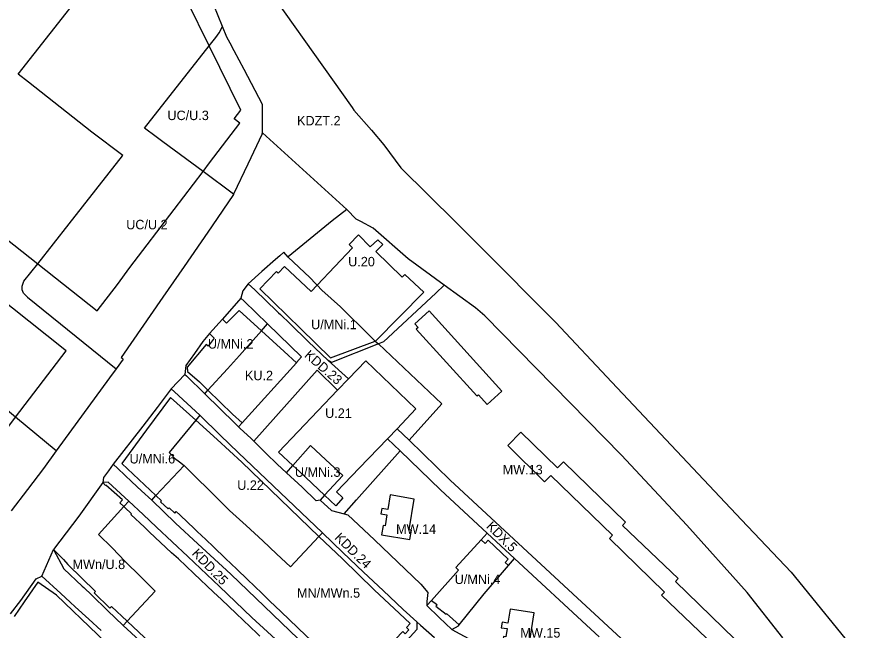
# Model space of a CAD drawing. Extents: x 7425067 to 7426806, y 5549054 to 5550619.
# Drawn here: x 7426359 to 7426806.4, y 5549627.2 to 5549951.6 of the extents above; entities that cross this region are included whole.
import ezdxf

# ---------------------------------------------------------------- set-up
doc = ezdxf.new("R2010")
doc.units = 0
for name, color, linetype in [('LIN_Linia Zabudowy Nieprzekraczalna', 7, 'Continuous'), ('LIN_linia zabudowy obowiązująca', 7, 'Continuous'), ('LIN_linie_rozgraniczajace', 7, 'Continuous'), ('TXT_Oznaczenia_przeznaczen', 7, 'Continuous')]:
    doc.layers.add(name, color=color, linetype=linetype)

msp = doc.modelspace()

# ---------------------------------------------------------------- linework, layer by layer
at = {"layer": 'LIN_Linia Zabudowy Nieprzekraczalna'}
for points in [[(7426574.3701, 5549805.9242), (7426564.36, 5549815.27), (7426562.95, 5549813.85), (7426548.97, 5549827.49), (7426552.62, 5549831.22), (7426550.08, 5549833.7), (7426545.97, 5549829.96), (7426539.76, 5549836.22), (7426534.88, 5549831.19), (7426536.67, 5549829.37), (7426517.9345, 5549809.6705)], [(7426548.7684, 5549780.0786), (7426574.3701, 5549805.9242)], [(7426525.0284, 5549771.1488), (7426548.73, 5549780.0641), (7426548.7684, 5549780.0786)], [(7426440.2683, 5549750.2788), (7426427.54, 5549733.14), (7426414.5439, 5549715.4054)], [(7426538.0268, 5549599.6257), (7426544.74, 5549606.81), (7426559.36, 5549622.35), (7426563.29, 5549626.51), (7426564.58, 5549625.28), (7426566.52, 5549627.33), (7426565.24, 5549628.54), (7426567.25, 5549630.67), (7426561.59, 5549636.03), (7426548.12, 5549648.56), (7426531.28, 5549664.88), (7426518.913, 5549676.7566), (7426478.07, 5549715.98), (7426464.99, 5549727.97), (7426453.6444, 5549738.2083), (7426440.2683, 5549750.2788)], [(7426414.5439, 5549715.4054), (7426432.6235, 5549698.32), (7426435.47, 5549695.63), (7426435, 5549695.1), (7426439.11, 5549691.3), (7426439.66, 5549691.9), (7426442.66, 5549689.14)], [(7426413.4908, 5549694.479), (7426414.9602, 5549696.0898), (7426406.0488, 5549703.8503), (7426405.97, 5549703.75), (7426404.43, 5549705.26), (7426391.71, 5549687.39), (7426378.39, 5549669.82)], [(7426426.5198, 5549681.588), (7426426.54, 5549681.61), (7426419.36, 5549688.41), (7426419.7, 5549688.77), (7426416.1, 5549692.08), (7426415.6453, 5549692.4981), (7426413.4908, 5549694.479)], [(7426442.66, 5549689.14), (7426443.3845, 5549689.9043), (7426445.3474, 5549688.063), (7426453.04, 5549680.77), (7426454.4822, 5549679.4051), (7426458.9674, 5549675.0954), (7426463.0302, 5549671.2622), (7426469.4399, 5549665.1439), (7426475.3736, 5549659.3903), (7426481.0322, 5549653.9703), (7426484.8352, 5549650.3881), (7426488.7822, 5549646.5623), (7426492.7561, 5549642.6881), (7426498.8215, 5549636.8419), (7426511.9317, 5549624.3494), (7426519.6144, 5549617.2769), (7426525.2257, 5549611.917), (7426529.8193, 5549607.5641), (7426538.0268, 5549599.6257)], [(7426487.6123, 5549624.0024), (7426486.1182, 5549625.4194), (7426475.0591, 5549635.938), (7426467.2851, 5549643.3718), (7426463.1098, 5549647.3578), (7426452.6961, 5549657.1819), (7426444.552, 5549664.9118), (7426440.8931, 5549668.0124), (7426429.2534, 5549678.9537), (7426426.5198, 5549681.588)], [(7426619.2615, 5549661.3404), (7426617.5, 5549663.0032), (7426619.13, 5549664.74), (7426608.5386, 5549674.7495), (7426606.8998, 5549673.0091), (7426604.7557, 5549675.0331)], [(7426378.39, 5549669.82), (7426383.61, 5549664.48), (7426386.01, 5549661.89), (7426400.55, 5549647.58), (7426399.82, 5549646.84), (7426408.17, 5549638.76), (7426409.02, 5549639.64), (7426417.3229, 5549631.8468), (7426444.72, 5549606.26), (7426460.04, 5549591.38), (7426467.6303, 5549584.2897), (7426477.25, 5549575.34), (7426477.5977, 5549575.714)], [(7426370.03, 5549652.54), (7426362.92, 5549642.18), (7426357.542, 5549634.3437)], [(7426413.6, 5549613.31), (7426401.6206, 5549624.8545), (7426380, 5549645.69), (7426370.03, 5549652.54)], [(7426578.398, 5549642.8706), (7426581.1286, 5549640.8896), (7426581.3939, 5549640.645), (7426580.79, 5549639.9), (7426586.15, 5549635.55), (7426586.4957, 5549635.9758), (7426593.1091, 5549629.933)]]:
    msp.add_lwpolyline(points, dxfattribs=at)
at = {"layer": 'LIN_linia zabudowy obowiązująca'}
for points in [[(7426477.01, 5549895.39), (7426474.02, 5549897.65), (7426477.58, 5549902.29), (7426460.7502, 5549936.2646), (7426449.26, 5549959.46), (7426441.71, 5549965.17), (7426422.62, 5549980.1), (7426417.53, 5549983.98), (7426417.78, 5549984.29), (7426412.3933, 5549988.5089), (7426402.65, 5549996.14), (7426401.75, 5549997.21), (7426363.71, 5550027.01)], [(7426265.8603, 5549903.2149), (7426320, 5549860.43), (7426369.9917, 5549820.9231), (7426401.5017, 5549796.0217)], [(7426442.32, 5549849.64), (7426457.5123, 5549869.788), (7426460.99, 5549874.4), (7426477.01, 5549895.39)], [(7426385.0744, 5549774.9325), (7426384.36, 5549775.5), (7426281.18, 5549857.47)], [(7426401.5017, 5549796.0217), (7426412.16, 5549809.96), (7426418.81, 5549818.96), (7426442.32, 5549849.64)], [(7426500.6894, 5549819.4961), (7426497.35, 5549816.03), (7426496.46, 5549816.89), (7426487.582, 5549807.7023)], [(7426514.6954, 5549806.2648), (7426500.6894, 5549819.4961)], [(7426487.582, 5549807.7023), (7426509.21, 5549786.59), (7426525.0284, 5549771.1488)], [(7426517.9345, 5549809.6705), (7426514.6954, 5549806.2648)], [(7426476.6068, 5549796.3443), (7426469.9988, 5549789.5057)], [(7426506.9179, 5549768.6433), (7426500.4, 5549774.6), (7426488.4327, 5549785.5368), (7426476.6068, 5549796.3443)], [(7426577.29, 5549796.04), (7426569.61, 5549789.15), (7426571.33, 5549787.24), (7426570.38, 5549786.39), (7426602.55, 5549751.06), (7426603.29, 5549751.72), (7426607.92, 5549746.56)], [(7426615.7, 5549753.6), (7426577.29, 5549796.04)], [(7426467.79, 5549791.63), (7426460.92, 5549784.18), (7426463.48, 5549781.67), (7426460.24, 5549777.47)], [(7426467.79, 5549791.63), (7426469.62, 5549789.87), (7426469.9988, 5549789.5057)], [(7426460.24, 5549777.47), (7426459.2, 5549778.34), (7426449.05, 5549766.29)], [(7426346.0059, 5549723.7436), (7426358.2546, 5549739.7922), (7426385.0744, 5549774.9325)], [(7426478.1914, 5549736.7716), (7426506.9179, 5549768.6433)], [(7426543.62, 5549769.68), (7426534.51, 5549760.15), (7426528.73, 5549754.1)], [(7426560.25, 5549733.73), (7426570.2485, 5549744.1648), (7426543.62, 5549769.68)], [(7426449.05, 5549766.29), (7426449.32, 5549763.94), (7426455.57, 5549758.5), (7426460.0965, 5549754.0969), (7426473.17, 5549741.38), (7426478.1914, 5549736.7716)], [(7426528.73, 5549754.1), (7426497.5593, 5549721.3931)], [(7426607.92, 5549746.56), (7426615.7, 5549753.6)], [(7426540.26, 5549712.91), (7426560.25, 5549733.73)], [(7426739.09, 5549622.43), (7426707.55, 5549652.9), (7426709.02, 5549654.42), (7426679.63, 5549682.6), (7426681.22, 5549684.26), (7426648.41, 5549716.18), (7426645.18, 5549712.98), (7426625.8, 5549731.91), (7426618.88, 5549724.83), (7426638.3, 5549705.72), (7426641.59, 5549709.06), (7426674.27, 5549677.34), (7426672.66, 5549675.68), (7426701.89, 5549647.32), (7426700.25, 5549645.63), (7426732.19, 5549615.19), (7426739.09, 5549622.43)], [(7426497.5593, 5549721.3931), (7426505.1277, 5549714.2694), (7426508.58, 5549711.02), (7426521.8294, 5549698.5492), (7426527.832, 5549692.8993)], [(7426528.216, 5549700.2875), (7426540.26, 5549712.91)], [(7426531.56, 5549697.14), (7426528.216, 5549700.2875)], [(7426531.56, 5549697.14), (7426528.07, 5549693.17), (7426527.832, 5549692.8993)], [(7426555.35, 5549691), (7426552.18, 5549691.55), (7426551.69, 5549688.67), (7426554.88, 5549688.13), (7426553.9, 5549682.43), (7426552.88, 5549682.61), (7426552.03, 5549677.65), (7426567, 5549675.08), (7426567.86, 5549680.09), (7426566.6, 5549680.3), (7426569.38, 5549696.51), (7426556.67, 5549698.69)], [(7426556.67, 5549698.69), (7426555.35, 5549691)], [(7426618.96, 5549630.88), (7426615.83, 5549631.36), (7426615.39, 5549628.48), (7426618.53, 5549628), (7426617.87, 5549623.69), (7426616.67, 5549623.88), (7426615.9, 5549618.82), (7426630.98, 5549616.53), (7426631.74, 5549621.55), (7426630.6, 5549621.72), (7426632.82, 5549636.33), (7426620.09, 5549638.27)], [(7426620.09, 5549638.27), (7426618.96, 5549630.88)]]:
    msp.add_lwpolyline(points, dxfattribs=at)
at = {"layer": 'LIN_linie_rozgraniczajace'}
for points in [[(7426359.67, 5549921.34), (7426412.3933, 5549988.5089), (7426413.76, 5549990.25)], [(7426480.4904, 5549982.4504), (7426536.4027, 5549903.6836)], [(7426467.83, 5549946.55), (7426463.2, 5549957.77)], [(7426466.01, 5549943.15), (7426467.83, 5549946.55)], [(7426470.2, 5549940.81), (7426467.83, 5549946.55)], [(7426464.23, 5549940.69), (7426466.01, 5549943.15)], [(7426426.51, 5549892.72), (7426460.7502, 5549936.2646), (7426464.23, 5549940.69)], [(7426471.87, 5549937.71), (7426470.2, 5549940.81)], [(7426474.03, 5549933.66), (7426471.87, 5549937.71)], [(7426479.33, 5549923.8), (7426474.03, 5549933.66)], [(7426488.96, 5549905.28), (7426479.33, 5549923.8)], [(7426365.08, 5549917.08), (7426359.67, 5549921.34)], [(7426398.67, 5549890.59), (7426365.08, 5549917.08)], [(7426489.01, 5549890.28), (7426488.96, 5549905.28)], [(7426536.4027, 5549903.6836), (7426537.3873, 5549902.2965)], [(7426537.3873, 5549902.2965), (7426546.67, 5549891.59)], [(7426432.69, 5549888.15), (7426426.51, 5549892.72)], [(7426415.08, 5549878.17), (7426398.67, 5549890.59)], [(7426436.21, 5549885.55), (7426432.69, 5549888.15)], [(7426488.9, 5549889.63), (7426481.28, 5549873.735)], [(7426488.9, 5549889.63), (7426489.01, 5549890.28)], [(7426533.71, 5549849.65), (7426489.01, 5549890.28)], [(7426546.67, 5549891.59), (7426553.32, 5549883.92)], [(7426473.66, 5549857.84), (7426457.5123, 5549869.788), (7426436.21, 5549885.55)], [(7426553.32, 5549883.92), (7426562.25, 5549871.78)], [(7426386.71, 5549842.14), (7426414.96, 5549878.02)], [(7426414.96, 5549878.02), (7426415.08, 5549878.17)], [(7426481.28, 5549873.735), (7426473.66, 5549857.84)], [(7426562.25, 5549871.78), (7426591.4086, 5549842.9985)], [(7426473.58, 5549857.68), (7426462.35, 5549841.06)], [(7426473.66, 5549857.84), (7426473.58, 5549857.68)], [(7426533.71, 5549849.65), (7426525.9, 5549843.67)], [(7426538.52, 5549844.56), (7426533.71, 5549849.65)], [(7426525.9, 5549843.67), (7426514.265, 5549834.16)], [(7426541.14, 5549843.27), (7426538.52, 5549844.56)], [(7426547.67, 5549839.86), (7426541.14, 5549843.27)], [(7426362.74, 5549811.72), (7426369.9917, 5549820.9231), (7426386.71, 5549842.14)], [(7426462.35, 5549841.06), (7426460.08, 5549837.7)], [(7426566.09, 5549823.62), (7426547.67, 5549839.86)], [(7426591.4086, 5549842.9985), (7426604.2348, 5549830.0944)], [(7426460.08, 5549837.7), (7426447.48, 5549819.5)], [(7426514.265, 5549834.16), (7426502.63, 5549824.65)], [(7426379.83, 5549722.02), (7426358.2546, 5549739.7922), (7426349.82, 5549746.74), (7426335.58, 5549742.45), (7426334.69, 5549743.18), (7426305.14, 5549767.39), (7426266.81, 5549798.71), (7426258.9, 5549804.84), (7426250.64, 5549811.51), (7426246.9144, 5549814.5236), (7426237.14, 5549822.43), (7426233.21, 5549825.6), (7426232.39, 5549830.98), (7426226.79, 5549830.23)], [(7426604.2348, 5549830.0944), (7426644.021, 5549790.0663)], [(7426498.13, 5549825.19), (7426495.93, 5549823.31)], [(7426500.33, 5549827.07), (7426498.13, 5549825.19)], [(7426502.52, 5549824.53), (7426500.33, 5549827.07)], [(7426495.93, 5549823.31), (7426488.69, 5549816.845)], [(7426502.63, 5549824.65), (7426502.52, 5549824.53)], [(7426502.52, 5549824.53), (7426514.09, 5549813.69)], [(7426585.19, 5549809.67), (7426566.09, 5549823.62)], [(7426447.48, 5549819.5), (7426436.3, 5549803.33)], [(7426488.69, 5549816.845), (7426481.45, 5549810.38)], [(7426514.09, 5549813.69), (7426517.275, 5549810.36)], [(7426361.83, 5549807.26), (7426361.85, 5549809.21)], [(7426362.45, 5549805.4), (7426361.83, 5549807.26)], [(7426361.85, 5549809.21), (7426362.74, 5549811.72)], [(7426481.45, 5549810.38), (7426478.62, 5549806.73)], [(7426481.45, 5549810.38), (7426484.94, 5549807.11)], [(7426517.275, 5549810.36), (7426517.9345, 5549809.6705), (7426520.46, 5549807.03)], [(7426585.19, 5549809.67), (7426580.69, 5549805.38)], [(7426601.75, 5549797.59), (7426585.19, 5549809.67)], [(7426364.59, 5549803.36), (7426362.45, 5549805.4)], [(7426364.59, 5549803.36), (7426411.51, 5549765.48)], [(7426436.3, 5549803.33), (7426414.19, 5549771.39)], [(7426478.62, 5549806.73), (7426477.615, 5549802.71)], [(7426484.94, 5549807.11), (7426496.75, 5549795.79)], [(7426520.46, 5549807.03), (7426525.375, 5549802.58)], [(7426580.69, 5549805.38), (7426553.12, 5549779.65)], [(7426477.615, 5549802.71), (7426467.79, 5549791.63)], [(7426477.615, 5549802.71), (7426479.33, 5549801.25)], [(7426479.33, 5549801.25), (7426491.72, 5549789.23)], [(7426525.375, 5549802.58), (7426530.29, 5549798.13)], [(7426496.75, 5549795.79), (7426497.48, 5549795.1)], [(7426497.48, 5549795.1), (7426498.52, 5549794.15)], [(7426498.52, 5549794.15), (7426503.63, 5549789.23)], [(7426530.29, 5549798.13), (7426535.575, 5549792.975)], [(7426606.77, 5549793.48), (7426601.75, 5549797.59)], [(7426467.79, 5549791.63), (7426460.92, 5549784.18)], [(7426535.575, 5549792.975), (7426540.86, 5549787.82)], [(7426642.925, 5549756.6), (7426606.77, 5549793.48)], [(7426644.021, 5549790.0663), (7426673.9296, 5549758.3678)], [(7426476.82, 5549772.49), (7426488.4327, 5549785.5368), (7426491.72, 5549789.23)], [(7426491.72, 5549789.23), (7426509.7274, 5549771.7604)], [(7426503.63, 5549789.23), (7426513.17, 5549779.93)], [(7426540.86, 5549787.82), (7426546.79, 5549781.9), (7426548.73, 5549780.0641), (7426550.33, 5549778.55), (7426525.58, 5549768.72), (7426523.7, 5549769.75)], [(7426459.175, 5549782.03), (7426457.43, 5549779.88)], [(7426460.92, 5549784.18), (7426459.175, 5549782.03)], [(7426457.43, 5549779.88), (7426452.965, 5549773.54)], [(7426513.17, 5549779.93), (7426523.7, 5549769.75)], [(7426553.12, 5549779.65), (7426550.33, 5549778.55)], [(7426583.95, 5549746.83), (7426550.33, 5549778.55)], [(7426452.965, 5549773.54), (7426448.5, 5549767.2)], [(7426475.23, 5549770.7), (7426476.82, 5549772.49)], [(7426509.7274, 5549771.7604), (7426506.96, 5549768.69)], [(7426415.19, 5549770.57), (7426411.51, 5549765.48)], [(7426414.19, 5549771.39), (7426414.65, 5549771.01)], [(7426414.65, 5549771.01), (7426415.19, 5549770.57)], [(7426448.5, 5549767.2), (7426447.97, 5549762.34)], [(7426470.48, 5549765.48), (7426475.23, 5549770.7)], [(7426506.96, 5549768.69), (7426506.9179, 5549768.6433), (7426478.1914, 5549736.7716), (7426476.3719, 5549734.7528)], [(7426523.7, 5549769.75), (7426534.51, 5549760.15)], [(7426411.51, 5549765.48), (7426408.03, 5549760.64)], [(7426458.43, 5549752.27), (7426460.0965, 5549754.0969), (7426470.48, 5549765.48)], [(7426484.3733, 5549727.0962), (7426517.8611, 5549764.702)], [(7426528.73, 5549754.1), (7426517.8611, 5549764.702)], [(7426408.03, 5549760.64), (7426379.83, 5549722.02)], [(7426447.97, 5549762.34), (7426440.71, 5549754.86)], [(7426447.97, 5549762.34), (7426448.86, 5549761.66)], [(7426448.86, 5549761.66), (7426458.43, 5549752.27)], [(7426534.51, 5549760.15), (7426528.73, 5549754.1)], [(7426673.9296, 5549758.3678), (7426742.5859, 5549685.6028)], [(7426440.71, 5549754.86), (7426433.185, 5549744.935)], [(7426440.71, 5549754.86), (7426442.46, 5549753.23)], [(7426679.08, 5549719.72), (7426642.925, 5549756.6)], [(7426442.46, 5549753.23), (7426455.81, 5549740.83)], [(7426458.43, 5549752.27), (7426474.5, 5549736.53)], [(7426433.185, 5549744.935), (7426425.66, 5549735.01)], [(7426566.59, 5549727.61), (7426583.95, 5549746.83)], [(7426455.81, 5549740.83), (7426453.6444, 5549738.2083), (7426439.57, 5549721.17)], [(7426455.81, 5549740.83), (7426466.79, 5549730.16)], [(7426474.5, 5549736.53), (7426476.3719, 5549734.7528), (7426477.07, 5549734.09)], [(7426425.66, 5549735.01), (7426410.02, 5549714.99)], [(7426477.07, 5549734.09), (7426482.96, 5549728.49)], [(7426560.25, 5549733.73), (7426555.26, 5549728.39)], [(7426560.25, 5549733.73), (7426566.59, 5549727.61)], [(7426466.79, 5549730.16), (7426476.04, 5549721.18)], [(7426482.96, 5549728.49), (7426484.3733, 5549727.0962), (7426490.9, 5549720.66)], [(7426561.83, 5549722.04), (7426555.26, 5549728.39)], [(7426566.59, 5549727.61), (7426588.34, 5549706.58)], [(7426501.77, 5549710.44), (7426505.1277, 5549714.2694), (7426514.37, 5549724.81)], [(7426514.37, 5549724.81), (7426522.6, 5549717.23)], [(7426379.83, 5549722.02), (7426373.06, 5549712.75)], [(7426439.57, 5549721.17), (7426441.01, 5549719.655)], [(7426441.01, 5549719.655), (7426442.45, 5549718.14)], [(7426442.45, 5549718.14), (7426445.015, 5549716.165)], [(7426476.04, 5549721.18), (7426520.68, 5549678.64)], [(7426490.9, 5549720.66), (7426496.85, 5549715.06)], [(7426538.74, 5549696.07), (7426561.83, 5549722.04)], [(7426572.51, 5549711.72), (7426561.83, 5549722.04)], [(7426696.385, 5549701.205), (7426679.08, 5549719.72)], [(7426410.02, 5549714.99), (7426407.41, 5549711.465)], [(7426410.02, 5549714.99), (7426412.51, 5549712.63)], [(7426430.39, 5549695.95), (7426432.6235, 5549698.32), (7426447.58, 5549714.19)], [(7426445.015, 5549716.165), (7426447.58, 5549714.19)], [(7426447.58, 5549714.19), (7426449.26, 5549712.535)], [(7426496.85, 5549715.06), (7426501.77, 5549710.44)], [(7426522.6, 5549717.23), (7426531.48, 5549709.01)], [(7426373.06, 5549712.75), (7426364.545, 5549701.505)], [(7426407.41, 5549711.465), (7426404.8, 5549707.94)], [(7426412.51, 5549712.63), (7426419.83, 5549705.68)], [(7426449.26, 5549712.535), (7426450.94, 5549710.88)], [(7426450.94, 5549710.88), (7426454.945, 5549706.93)], [(7426501.77, 5549710.44), (7426509.92, 5549702.76)], [(7426531.48, 5549709.01), (7426521.8294, 5549698.5492), (7426519.45, 5549695.97)], [(7426583.19, 5549701.4), (7426572.51, 5549711.72)], [(7426404.43, 5549705.26), (7426391.71, 5549687.39)], [(7426404.8, 5549707.94), (7426404.43, 5549705.26)], [(7426407.3768, 5549705.5397), (7426404.43, 5549705.26)], [(7426416.1513, 5549697.3955), (7426407.3768, 5549705.5397)], [(7426419.83, 5549705.68), (7426424.94, 5549700.84)], [(7426454.945, 5549706.93), (7426459.555, 5549702.385)], [(7426588.34, 5549706.58), (7426653.31, 5549646.475)], [(7426364.545, 5549701.505), (7426356.03, 5549690.26)], [(7426424.94, 5549700.84), (7426430.39, 5549695.95)], [(7426459.555, 5549702.385), (7426463.2125, 5549698.779)], [(7426509.92, 5549702.76), (7426517.48, 5549695.61)], [(7426607.93, 5549678.54), (7426583.19, 5549701.4)], [(7426713.69, 5549682.69), (7426696.385, 5549701.205)], [(7426418.2967, 5549695.4043), (7426415.6453, 5549692.4981), (7426402.19, 5549677.75)], [(7426418.2967, 5549695.4043), (7426416.1513, 5549697.3955)], [(7426425.8, 5549688.44), (7426418.2967, 5549695.4043)], [(7426430.39, 5549695.95), (7426443.02, 5549683.71)], [(7426463.2125, 5549698.779), (7426471.6, 5549690.54)], [(7426519.45, 5549695.97), (7426517.48, 5549695.61)], [(7426519.45, 5549695.97), (7426525.57, 5549690.53)], [(7426532.2235, 5549688.7084), (7426538.74, 5549696.07)], [(7426391.71, 5549687.39), (7426378.39, 5549669.82)], [(7426432.9, 5549681.65), (7426425.8, 5549688.44)], [(7426471.6, 5549690.54), (7426480.37, 5549682.45)], [(7426525.57, 5549690.53), (7426532.2235, 5549688.7084), (7426534.19, 5549688.17)], [(7426534.19, 5549688.17), (7426548.23, 5549674.96)], [(7426443.02, 5549683.71), (7426454.72, 5549672.89)], [(7426480.37, 5549682.45), (7426489.14, 5549674.36)], [(7426745.61, 5549647.09), (7426713.69, 5549682.69)], [(7426742.5859, 5549685.6028), (7426768.7838, 5549657.8369)], [(7426402.19, 5549677.75), (7426409.36, 5549670.65)], [(7426449.52, 5549666.05), (7426432.9, 5549681.65)], [(7426503.84, 5549660.69), (7426518.913, 5549676.7566), (7426520.68, 5549678.64)], [(7426520.68, 5549678.64), (7426531.49, 5549668.27)], [(7426591.42, 5549660.3), (7426604.7557, 5549675.0331), (7426607.93, 5549678.54)], [(7426622.44, 5549665.05), (7426607.93, 5549678.54)], [(7426489.14, 5549674.36), (7426496.49, 5549667.525)], [(7426548.23, 5549674.96), (7426572.86, 5549651.48)], [(7426372.27, 5549655.8), (7426378.39, 5549669.82)], [(7426378.39, 5549669.82), (7426383.89, 5549659.63)], [(7426409.36, 5549670.65), (7426416.36, 5549663.44)], [(7426454.72, 5549672.89), (7426472.2007, 5549656.8053)], [(7426466.33, 5549650.29), (7426449.52, 5549666.05)], [(7426496.49, 5549667.525), (7426503.84, 5549660.69)], [(7426531.49, 5549668.27), (7426542.4, 5549657.85)], [(7426606.4, 5549646.33), (7426619.2615, 5549661.3404), (7426622.44, 5549665.05)], [(7426662.87, 5549627.68), (7426622.44, 5549665.05)], [(7426383.89, 5549659.63), (7426393.61, 5549650.53)], [(7426416.36, 5549663.44), (7426424.5, 5549655.63)], [(7426592.77, 5549658.85), (7426591.42, 5549660.3)], [(7426369.22, 5549654.3), (7426372.27, 5549655.8)], [(7426372.27, 5549655.8), (7426382.25, 5549646.49)], [(7426424.5, 5549655.63), (7426432.23, 5549647.82)], [(7426472.2007, 5549656.8053), (7426516.68, 5549614.14)], [(7426542.4, 5549657.85), (7426552.93, 5549648.09)], [(7426575.96, 5549640.16), (7426578.398, 5549642.8706), (7426592.77, 5549658.85)], [(7426768.7838, 5549657.8369), (7426806.41, 5549611.72)], [(7426361.05, 5549642.83), (7426369.22, 5549654.3)], [(7426572.86, 5549651.48), (7426576.48, 5549647.14)], [(7426382.25, 5549646.49), (7426387.16, 5549641.91)], [(7426393.61, 5549650.53), (7426394.43, 5549649.75)], [(7426394.43, 5549649.75), (7426398.7, 5549645.72)], [(7426415.31, 5549629.69), (7426417.3229, 5549631.8468), (7426432.23, 5549647.82)], [(7426474.71, 5549642.22), (7426466.33, 5549650.29)], [(7426552.93, 5549648.09), (7426563.52, 5549638.07)], [(7426576.48, 5549647.14), (7426576.07, 5549642.27)], [(7426592.75, 5549629.49), (7426593.1091, 5549629.933), (7426606.4, 5549646.33)], [(7426653.31, 5549646.475), (7426718.28, 5549586.37)], [(7426764.4032, 5549623.1806), (7426745.61, 5549647.09)], [(7426355.61, 5549635.73), (7426361.05, 5549642.83)], [(7426387.16, 5549641.91), (7426389.82, 5549639.43)], [(7426398.7, 5549645.72), (7426406.97, 5549637.52)], [(7426483.42, 5549633.83), (7426474.71, 5549642.22)], [(7426576.07, 5549642.27), (7426575.96, 5549640.16)], [(7426389.82, 5549639.43), (7426397, 5549632.91)], [(7426406.97, 5549637.52), (7426415.31, 5549629.69)], [(7426563.52, 5549638.07), (7426570.6214, 5549631.6641), (7426572.71, 5549629.78)], [(7426575.96, 5549640.16), (7426582.57, 5549633.82)], [(7426397, 5549632.91), (7426403.56, 5549626.95)], [(7426499.92, 5549618.67), (7426483.42, 5549633.83)], [(7426582.57, 5549633.82), (7426589.18, 5549627.48)], [(7426415.31, 5549629.69), (7426423.85, 5549621.67)], [(7426570.6214, 5549631.6641), (7426570.6275, 5549627.4872)], [(7426572.71, 5549629.78), (7426579.98, 5549623.28)], [(7426589.18, 5549627.48), (7426592.75, 5549629.49)], [(7426570.6275, 5549627.4872), (7426556.37, 5549611.79)], [(7426589.18, 5549627.48), (7426599.99, 5549621.71)], [(7426667.17, 5549623.56), (7426662.87, 5549627.68)]]:
    msp.add_lwpolyline(points, dxfattribs=at)

# ---------------------------------------------------------------- texts
at = {"layer": 'TXT_Oznaczenia_przeznaczen'}
for s, p in [('UC/U.3', (7426438.6716, 5549896.9818)), ('KDZT.2', (7426507.306, 5549894.1678)), ('UC/U.2', (7426416.854, 5549839.214)), ('U.20', (7426534.3638, 5549819.6168)), ('U/MNi.1', (7426514.7392, 5549786.3774)), ('U/MNi.2', (7426460.1037, 5549776.1034)), ('KU.2', (7426479.7099, 5549759.3854)), ('U.21', (7426522.1608, 5549739.454)), ('U/MNi.6', (7426418.6317, 5549715.3564)), ('U/MNi.3', (7426506.1437, 5549708.2678)), ('MW.13', (7426616.1512, 5549709.5958)), ('U.22', (7426475.6124, 5549701.379)), ('MW.14', (7426559.7256, 5549678.1177)), ('MWn/U.8', (7426388.441, 5549659.4893)), ('U/MNi.4', (7426590.7587, 5549651.6008)), ('MN/MWn.5', (7426507.2591, 5549644.3633)), ('MW.15', (7426625.5283, 5549623.2646))]:
    msp.add_text(s, height=5, dxfattribs=at).set_placement(p)
for s, rotation, p in [('KDD.23', 318.967791, (7426510.8044, 5549772.0072)), ('KDX.5', 315.138735, (7426607.0927, 5549681.7325)), ('KDD.24', 315.530788, (7426526.8553, 5549675.6895)), ('KDD.25', 314.250611, (7426451.313, 5549667.3797))]:
    msp.add_text(s, height=5, rotation=rotation, dxfattribs=at).set_placement(p)

doc.saveas('drawing.dxf')
